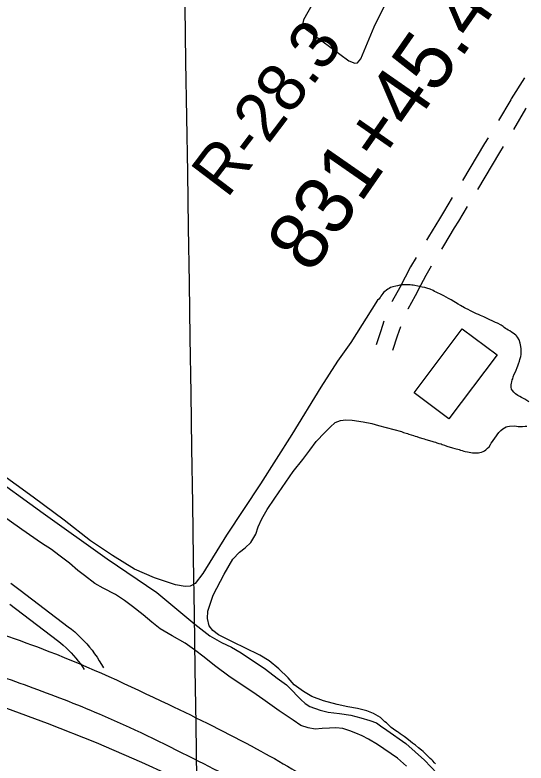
# Model space of a CAD drawing. Extents: x 3823584 to 3861785, y 301729 to 327625.
# Drawn here: x 3837921 to 3838799, y 321169 to 322453 of the extents above; entities that cross this region are included whole.
import ezdxf

# ---------------------------------------------------------------- set-up
doc = ezdxf.new("R2010")
doc.units = 0
for name, color, linetype in [('V-GRID-MAJR', 7, 'Continuous'), ('V-RIVR-EDGE', 7, 'Continuous'), ('V-RIVR-RANG-IDEN', 7, 'Continuous'), ('V-ROAD-CNTR', 7, 'Continuous'), ('V-SITE-OTLN', 7, 'Continuous'), ('V-SITE-VEGE', 7, 'Continuous'), ('V-SURV-IDEN', 7, 'Continuous'), ('V-TOPO-SHOR', 7, 'Continuous'), ('V-WETL-SWMP', 7, 'Continuous')]:
    doc.layers.add(name, color=color, linetype=linetype)

msp = doc.modelspace()

# ---------------------------------------------------------------- linework, layer by layer
at = {"layer": 'V-GRID-MAJR'}
msp.add_spline([(3838444.8910000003, 307319.343), (3838352.38, 313376.366), (3838259.823, 319436.473), (3838167.2660000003, 325496.576), (3838167.219, 325499.664)], degree=3, dxfattribs=at)
at = {"layer": 'V-RIVR-EDGE'}
msp.add_spline([(3836304.3756208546, 325474.18490968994), (3836346.414637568, 325438.3248399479), (3836389.407230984, 325406.0749957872), (3836417.6425015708, 325385.4333151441), (3836442.6682071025, 325366.7281829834), (3836470.247893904, 325340.94515767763), (3836497.8244014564, 325313.8763988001), (3836554.9028376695, 325258.4483785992), (3836598.5128638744, 325215.91107623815), (3836636.356164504, 325181.10248193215), (3836681.25510353, 325139.84773389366), (3836737.070060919, 325093.42302794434), (3836790.9421113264, 325041.2172897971), (3836840.3252216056, 324993.52274652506), (3836889.068644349, 324947.1155264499), (3836934.613629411, 324907.1449223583), (3836980.8110190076, 324871.0299293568), (3837015.471778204, 324849.0866188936), (3837040.494304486, 324829.09575316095), (3837085.3916538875, 324787.1981383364), (3837143.7621821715, 324734.3384060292), (3837181.60866205, 324700.815545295), (3837223.2932671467, 324659.5687453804), (3837272.052586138, 324619.5901931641), (3837314.3832372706, 324579.6275371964), (3837346.4455057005, 324546.7618498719), (3837364.398086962, 324527.4313367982), (3837395.83179523, 324500.35304017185), (3837442.024415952, 324462.30944681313), (3837492.7139249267, 324422.9689925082), (3837554.3051456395, 324372.67277922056), (3837573.562535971, 324361.05348832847), (3837583.2007688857, 324359.1010435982), (3837596.685075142, 324352.6389936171), (3837621.0774516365, 324337.7926517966), (3837648.0333471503, 324319.7256175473), (3837677.5368654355, 324292.00922300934), (3837718.5754244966, 324249.4782791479), (3837753.847257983, 324214.6760433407), (3837781.426944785, 324188.89301803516), (3837800.047826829, 324179.8467839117), (3837819.9544424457, 324170.79737053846), (3837850.7214395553, 324134.0776617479), (3837874.448694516, 324110.2327745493), (3837909.0728923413, 324073.5035280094), (3837941.7780275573, 324040.63625106), (3837989.872225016, 323991.65915346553), (3838022.5821291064, 323960.7204768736), (3838034.1219387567, 323947.83452790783), (3838046.301435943, 323933.66125574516), (3838066.8302532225, 323916.25298453), (3838089.9146413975, 323892.40968695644), (3838140.5946126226, 323849.2120319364), (3838186.144366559, 323811.1700282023), (3838215.652653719, 323785.38223402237), (3838265.675451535, 323736.40036755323), (3838297.1043909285, 323707.3934705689), (3838336.8747022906, 323671.9372406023), (3838359.952731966, 323645.5224758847), (3838385.6228939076, 323627.4586208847), (3838404.2374174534, 323615.8409196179), (3838421.5598489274, 323601.65493045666), (3838441.441030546, 323582.31964850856), (3838460.0476059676, 323567.48761331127), (3838468.395336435, 323563.60974747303), (3838484.446340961, 323555.21273863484), (3838548.5883636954, 323496.55289863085), (3838595.4381578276, 323464.2935167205), (3838649.9785090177, 323422.37205752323), (3838701.302936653, 323379.8156796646), (3838749.433695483, 323345.62451814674), (3838798.2232173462, 323317.86043486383), (3838856.617590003, 323274.6437043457), (3838932.9883882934, 323221.7394625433), (3838989.4684672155, 323184.31330197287), (3839037.599226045, 323150.12214045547), (3839068.4186807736, 323134.6170356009), (3839093.417362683, 323104.98316807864), (3839110.730256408, 323086.93997820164), (3839122.930418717, 323081.1239742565), (3839143.464004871, 323065.6443033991), (3839172.3405526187, 323044.35816634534), (3839190.955076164, 323032.7404650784), (3839215.98555057, 323015.9639332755), (3839242.319244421, 323006.25575686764), (3839316.801182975, 322969.42795358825), (3839341.8396055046, 322955.86575571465), (3839371.3828644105, 322944.2210308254), (3839391.2910696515, 322935.81448423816), (3839417.6104568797, 322920.32050675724), (3839461.26181333, 322894.4977408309), (3839483.709693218, 322873.22750002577), (3839520.2990527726, 322851.27942068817), (3839555.6010891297, 322828.6916538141), (3839599.9048501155, 322806.7244989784), (3839718.698497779, 322751.1438747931), (3839768.138834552, 322726.5925358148), (3839807.9457072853, 322705.9222419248), (3839836.8508682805, 322696.20770701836), (3839865.0988558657, 322680.7089606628), (3839887.567400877, 322667.7959880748), (3839924.172656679, 322652.2765765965), (3839969.7621512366, 322630.306242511), (3840004.4324481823, 322612.2201327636), (3840037.8249596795, 322597.35153619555), (3840085.3541819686, 322579.87650073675), (3840108.4624145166, 322565.6762049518), (3840121.9212867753, 322548.928286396), (3840123.184765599, 322539.92497214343), (3840122.5260025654, 322533.4978939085), (3840117.9957321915, 322521.29455234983), (3840112.8353120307, 322514.2357347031), (3840095.465191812, 322509.1357202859), (3840089.6793907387, 322509.1500269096), (3840085.168195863, 322504.661086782), (3840084.5094328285, 322498.2340085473), (3840085.779270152, 322491.8021614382), (3840130.719539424, 322467.2619498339), (3840169.888314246, 322448.52184592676), (3840197.5093312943, 322439.45335705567), (3840209.076164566, 322437.4961434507), (3840231.586039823, 322441.2977072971), (3840246.3910513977, 322448.9755473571), (3840266.343766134, 322458.5692707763), (3840273.434376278, 322466.26618633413), (3840278.590027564, 322471.3964036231), (3840288.898150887, 322480.37110462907), (3840295.9808129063, 322484.8536862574), (3840301.7666139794, 322484.8393796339), (3840308.195281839, 322484.8234833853), (3840320.395444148, 322479.00747944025), (3840324.873256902, 322469.99621706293), (3840326.781192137, 322461.6341799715), (3840338.324181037, 322450.0339645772), (3840344.7401318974, 322444.87513404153), (3840366.580116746, 322437.7495521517), (3840385.842275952, 322428.05886161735), (3840421.7967168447, 322409.3267058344), (3840466.0957089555, 322385.43095064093), (3840492.411916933, 322368.65123958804), (3840506.526372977, 322357.0446656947), (3840533.4854477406, 322340.2633650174), (3840559.1778644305, 322331.1996450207), (3840587.441748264, 322322.12956652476), (3840611.8452521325, 322311.78329220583), (3840642.0218400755, 322296.27977697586), (3840678.615968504, 322276.2602979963), (3840712.637040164, 322255.60431073), (3840733.1753951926, 322242.05324023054), (3840784.5268464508, 322210.42559773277), (3840835.889425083, 322183.29802273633), (3840892.388579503, 322153.5862635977), (3840923.854080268, 322139.3653026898), (3840950.8242824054, 322127.08406951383), (3840989.3295253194, 322099.98828701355), (3841017.5727440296, 322082.56094030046), (3841061.238407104, 322062.5239754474), (3841092.6943701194, 322044.4458138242), (3841151.0982805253, 322005.0862840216), (3841210.7847452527, 321964.43784139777), (3841240.294622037, 321939.29291400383), (3841299.971549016, 321894.78727066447), (3841335.8926077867, 321862.55491237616), (3841374.3692374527, 321823.88752772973), (3841411.5712609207, 321789.72338983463), (3841444.922442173, 321758.1402568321), (3841469.94019958, 321736.22079074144), (3841482.124465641, 321723.9761189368), (3841496.2198461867, 321704.6551436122), (3841509.051747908, 321694.3374825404), (3841523.1773313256, 321687.23097614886), (3841573.8986327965, 321660.747857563), (3841623.970708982, 321631.69486145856), (3841667.623655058, 321606.5149623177), (3841696.5208679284, 321593.58609348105), (3841738.2626995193, 321575.48249786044), (3841787.074476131, 321556.7185495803), (3841815.992354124, 321552.1469489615), (3841851.3325414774, 321544.9879849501), (3841886.661601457, 321533.32895343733), (3841930.322495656, 321511.36338822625), (3841950.219573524, 321498.4567741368), (3841977.1818275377, 321482.9612070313), (3841998.380535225, 321476.4800815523), (3842052.9924195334, 321463.4876277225), (3842082.546805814, 321456.3429703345), (3842109.5185975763, 321444.7046039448), (3842146.1190845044, 321427.2565921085), (3842196.2006984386, 321402.06079671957), (3842241.1346092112, 321374.94911797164), (3842288.6336286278, 321345.2596135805), (3842321.375325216, 321327.17827270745), (3842366.940975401, 321295.56493683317), (3842395.188962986, 321280.06619047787), (3842429.2227516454, 321264.5531374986), (3842452.3516493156, 321258.7101099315), (3842470.9725313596, 321249.663875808)], degree=3, dxfattribs=at)
at = {"layer": 'V-ROAD-CNTR'}
for points in [[(3838795.988368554, 322344.5592854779), (3838773.2674139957, 322308.30635798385)], [(3838773.268413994, 322308.30835798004), (3838772.3924157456, 322306.91036077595), (3838751.136458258, 322271.31443196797)], [(3838798.6863631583, 322292.37238985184), (3838797.982364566, 322291.2503920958), (3838776.894406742, 322255.9344627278)], [(3838733.589493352, 322241.92849073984), (3838727.524505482, 322231.77351105), (3838689.6965811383, 322168.4816376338)], [(3838759.34544184, 322226.54652150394), (3838753.278453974, 322216.387541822), (3838715.448529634, 322153.0916684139)], [(3838672.081616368, 322139.23669612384), (3838656.9486466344, 322114.2427461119), (3838649.9216606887, 322102.6427693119)], [(3838697.7435650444, 322123.6987271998), (3838682.61059531, 322098.7027771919), (3838675.5816093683, 322087.09880040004)], [(3838649.9216606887, 322102.64176931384), (3838631.1266982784, 322071.61183137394), (3838627.754705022, 322066.03184253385)], [(3838675.5816093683, 322087.0998003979), (3838656.794646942, 322056.08186243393), (3838653.428653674, 322050.51387356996)], [(3838610.081740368, 322036.44790170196), (3838600.6207592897, 322020.22493414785), (3838591.092778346, 322002.34396990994), (3838582.1287962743, 321984.803004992), (3838569.0058225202, 321961.30205199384), (3838568.42582368, 321960.035054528)], [(3838635.99568854, 322021.33393192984), (3838626.8247068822, 322005.60896337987), (3838617.688725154, 321988.4639976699), (3838608.5907433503, 321970.6590332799), (3838595.783768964, 321947.72407914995), (3838595.703769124, 321947.54907949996)], [(3838554.4658516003, 321926.99512060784), (3838549.134862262, 321910.7471531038), (3838541.127878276, 321886.34320191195)], [(3838582.969794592, 321917.6431393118), (3838577.638805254, 321901.395171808), (3838569.6318212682, 321876.99122061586)], [(3837914.3287802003, 321477.55649889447), (3837930.3470027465, 321465.6516226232), (3838012.7239289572, 321402.6811217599), (3838018.2861308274, 321398.3887003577), (3838023.868097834, 321393.76665518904), (3838029.2856966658, 321388.96092887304), (3838034.543354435, 321383.971266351), (3838039.624461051, 321378.80080976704), (3838044.5259682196, 321373.4634935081), (3838049.2432002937, 321367.957365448), (3838053.766521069, 321362.29891065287), (3838058.0949127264, 321356.487913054), (3838062.2228218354, 321350.53386688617), (3838066.1459753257, 321344.43871785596), (3838069.857209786, 321338.2149486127), (3838073.2304969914, 321332.0932107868)], [(3837912.2889972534, 321441.6943773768), (3837994.450071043, 321378.88887824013), (3837999.5498691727, 321374.9532996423), (3838004.3419021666, 321370.985344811), (3838009.000303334, 321366.85307112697), (3838013.512645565, 321362.570733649), (3838017.871538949, 321358.135190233), (3838022.0800317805, 321353.5525064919), (3838026.1287997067, 321348.826634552), (3838030.013478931, 321343.96708934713), (3838033.7310872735, 321338.97608694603), (3838037.2751781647, 321333.8641331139), (3838040.0258204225, 321329.5906387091)]]:
    msp.add_lwpolyline(points, dxfattribs=at)
for points in [[(3837820.0383204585, 321416.434141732), (3837979.6760011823, 321360.54425351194), (3838184.128592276, 321269.847434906), (3838335.998288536, 321193.3505878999), (3838456.602047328, 321122.4437297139), (3838575.2558100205, 321042.7658890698), (3838676.193608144, 320972.2010302)], [(3838708.6275432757, 320880.458213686), (3838559.377841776, 320985.18000424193), (3838364.8532308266, 321104.28076603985), (3838228.3355038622, 321176.0496225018), (3838066.748827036, 321252.678469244), (3837945.153070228, 321300.111374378), (3837826.0583084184, 321341.8592908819), (3837697.7585650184, 321382.57520945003)]]:
    msp.add_spline(points, degree=3, dxfattribs=at)
at = {"layer": 'V-SITE-OTLN'}
msp.add_lwpolyline([(3838689.208, 321914.066), (3838748.946, 321869.065), (3838666.328, 321759.393), (3838606.589, 321804.393)], close=True, dxfattribs=at)
at = {"layer": 'V-SITE-VEGE'}
for points in [[(3838433.576, 322474.482), (3838416.379, 322444.098), (3838414.745, 322435.398), (3838417.096, 322431.03), (3838494.758, 322373.977), (3838505.0270000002, 322369.95900000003), (3838509.3850000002, 322370.329), (3838514.964, 322377.026), (3838538.244, 322432.316), (3838577.094, 322511.271)], [(3838604.998, 321989.051), (3838602.594, 321989.031), (3838599.886, 321989.305), (3838597.484, 321989.28500000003), (3838593.875, 321989.553), (3838587.867, 321989.5), (3838584.563, 321989.17), (3838577.969, 321987.609), (3838574.966, 321987.282), (3838569.873, 321985.731), (3838566.275, 321984.797), (3838563.5840000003, 321983.272), (3838561.191, 321982.049), (3838559.105, 321980.226), (3838556.119, 321978.096), (3838554.032, 321976.278), (3838552.846, 321974.461), (3838549.2800000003, 321969.923), (3838548.097, 321967.809), (3838546.018, 321965.085), (3838543.935, 321962.964), (3838497.867, 321890.739), (3838474.9050000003, 321858.487), (3838446.329, 321813.988), (3838396.844, 321732.375), (3838342.981, 321647.914), (3838284.347, 321559.717), (3838243.864, 321494.09500000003), (3838230.6950000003, 321476.939), (3838221.856, 321472.433), (3838213.433, 321471.589), (3838197.211, 321474.755), (3838160.934, 321486.646), (3838126.4560000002, 321501.699), (3838088.9620000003, 321524.987), (3838051.1780000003, 321550.355), (3838005.827, 321585.771), (3837952.776, 321625.191), (3837893.6010000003, 321667.618)], [(3838803.605, 321788.607), (3838796.654, 321793.053), (3838794.541, 321794.235), (3838790.619, 321796.005), (3838787.895, 321798.083), (3838784.876, 321799.558), (3838780.344, 321802.523), (3838777.616, 321805.202), (3838775.185, 321808.184), (3838773.964, 321810.277), (3838773.3310000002, 321813.878), (3838773.295, 321817.783), (3838773.87, 321820.794), (3838774.153, 321822.89900000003), (3838775.023, 321826.213), (3838775.906, 321828.324), (3838776.7800000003, 321831.337), (3838778.241, 321836.158), (3838780.307, 321840.082), (3838784.423, 321850.33400000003), (3838785.593, 321853.951), (3838787.3540000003, 321858.47500000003), (3838787.932, 321861.18200000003), (3838788.8140000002, 321863.29600000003), (3838789.687, 321866.607), (3838790.256, 321869.919), (3838790.514, 321874.728), (3838790.488, 321877.732), (3838790.164, 321880.431), (3838789.208, 321886.434), (3838788.5810000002, 321889.434), (3838786.725, 321895.128), (3838783.9790000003, 321899.91000000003), (3838782.4590000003, 321901.7), (3838780.946, 321903.189), (3838779.129, 321904.674), (3838776.7090000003, 321906.455), (3838773.688, 321908.231), (3838770.964, 321910.31), (3838767.947, 321911.784), (3838765.832, 321913.26900000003), (3838763.413, 321914.75), (3838761.2970000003, 321916.232), (3838759.4790000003, 321918.018), (3838755.85, 321920.39400000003), (3838749.812, 321923.64400000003), (3838746.497, 321924.814), (3838740.7600000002, 321927.76900000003), (3838736.541, 321929.231), (3838725.98, 321934.24700000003), (3838720.5500000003, 321936.602), (3838716.93, 321938.371), (3838713.913, 321939.547), (3838708.174, 321942.799), (3838703.349, 321944.859), (3838699.423, 321946.928), (3838695.202, 321948.693), (3838692.786, 321950.174), (3838686.443, 321953.723), (3838681.913, 321956.38800000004), (3838670.131, 321963.492), (3838665.2970000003, 321966.155), (3838657.45, 321970.289), (3838654.126, 321972.364), (3838644.166, 321977.083), (3838641.756, 321977.961), (3838639.036, 321979.741), (3838633.91, 321981.797), (3838628.184, 321983.55), (3838625.169, 321984.726), (3838620.653, 321985.586), (3838615.836, 321986.745), (3838604.998, 321989.051)], [(3838578.014, 321222.579), (3838574.9930000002, 321224.355), (3838567.434, 321229.696), (3838563.188, 321233.86100000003), (3838561.3740000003, 321235.348), (3838558.949, 321237.73), (3838556.528, 321239.514), (3838551.0700000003, 321244.871), (3838548.65, 321246.956), (3838536.806, 321253.854), (3838525.245, 321258.577), (3838509.522, 321262.429), (3838492.8030000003, 321265.397), (3838474.305, 321269.167), (3838451.169, 321275.538), (3838430.912, 321283.28), (3838416.502, 321291.58), (3838400.725, 321303.356), (3838390.198, 321315.3), (3838374.34, 321330.642), (3838357.682, 321344.007), (3838341.791, 321353.903), (3838316.12, 321366.623), (3838296.961, 321375.84500000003), (3838270.595, 321388.87200000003), (3838260.736, 321396.452), (3838254.938, 321404.409), (3838251.937, 321416.707), (3838252.509, 321429.773), (3838261.774, 321456.954), (3838280.597, 321492.696), (3838295.502, 321518.853), (3838306.7600000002, 321530.77), (3838316.4080000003, 321538.243), (3838326.4620000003, 321547.195), (3838334.961, 321561.507), (3838338.895, 321574.159), (3838344.919, 321588.188), (3838354.022, 321604.179), (3838367.3030000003, 321623.61), (3838398.955, 321668.984), (3838415.3140000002, 321689.488), (3838427.291, 321705.956), (3838438.465, 321720.352), (3838453.311, 321736.11100000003), (3838462.275, 321745.27), (3838471.233, 321753.042), (3838479.968, 321756.458), (3838489.186, 321757.988), (3838500.47, 321757.232), (3838519.367, 321754.25), (3838533.812, 321751.495), (3838545.477, 321748.26), (3838585.014, 321737.674), (3838588.332, 321736.201), (3838590.74, 321735.621), (3838592.8540000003, 321734.739), (3838595.262, 321734.159), (3838597.3710000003, 321733.276), (3838605.205, 321730.944), (3838608.521, 321729.77), (3838610.929, 321729.193), (3838615.449, 321727.73), (3838621.4760000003, 321725.981), (3838623.588, 321725.099), (3838626.899, 321724.226), (3838632.929, 321722.176), (3838638.651, 321720.726), (3838640.461, 321719.842), (3838643.47, 321719.266), (3838645.5810000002, 321718.38300000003), (3838649.198, 321717.214), (3838652.811, 321716.346), (3838654.9220000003, 321715.463), (3838658.838, 321714.29600000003), (3838662.7600000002, 321712.829), (3838672.701, 321709.913), (3838676.318, 321708.743), (3838683.846, 321706.708), (3838686.259, 321705.827), (3838688.968, 321705.252), (3838691.987, 321703.777), (3838694.094, 321703.494), (3838698.006, 321702.628), (3838701.316, 321702.05700000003), (3838703.722, 321701.776), (3838706.733, 321701.205), (3838708.838, 321700.922), (3838716.95, 321700.996), (3838719.645, 321701.92), (3838722.045, 321702.542), (3838725.042, 321703.472), (3838727.434, 321704.695), (3838729.525, 321706.214), (3838732.505, 321708.946), (3838735.183, 321711.674), (3838737.8540000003, 321715.604), (3838739.036, 321717.72000000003), (3838741.112, 321720.745), (3838741.997, 321722.553), (3838744.971, 321726.184)], [(3838744.971, 321726.184), (3838752.092, 321736.164), (3838755.366, 321739.498), (3838758.645, 321742.533), (3838764.627, 321745.591), (3838766.723, 321746.51300000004), (3838770.323, 321747.146), (3838779.336, 321747.22500000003), (3838785.056, 321746.074), (3838790.463, 321746.124), (3838792.5640000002, 321746.443), (3838797.068, 321746.783), (3838799.769, 321747.109)], [(3838643.109, 321167.574), (3838641.594, 321169.061), (3838638.557, 321172.641), (3838636.736, 321174.426), (3838634.315, 321176.507), (3838632.194, 321178.592), (3838628.8570000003, 321181.869), (3838626.127, 321184.849), (3838624.61, 321186.338), (3838621.8880000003, 321188.418), (3838619.463, 321190.798), (3838614.0160000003, 321195.257), (3838609.17, 321199.422), (3838607.3570000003, 321200.606), (3838603.7260000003, 321203.277), (3838596.765, 321208.925), (3838591.625, 321212.48), (3838589.204, 321214.565), (3838582.853, 321219.015), (3838579.826, 321221.391), (3838578.014, 321222.579)]]:
    msp.add_lwpolyline(points, dxfattribs=at)
at = {"layer": 'V-TOPO-SHOR'}
for points in [[(3837871.075, 321668.404), (3837969.75, 321597.918), (3838079.5840000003, 321519.037), (3838164.846, 321461.62200000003), (3838230.1920000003, 321407.395), (3838255.96, 321387.015), (3838275.93, 321375.593), (3838292.9420000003, 321367.86), (3838309.7460000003, 321357.84500000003), (3838351.636, 321329.837), (3838371.682, 321314.54600000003), (3838387.3880000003, 321303.151), (3838398.04, 321292.875), (3838405.529, 321284.5), (3838411.839, 321278.117), (3838419.3370000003, 321271.13300000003), (3838427.637, 321265.829), (3838445.551, 321259.377), (3838459.1210000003, 321256.424), (3838478.647, 321254.13), (3838497.769, 321250.848), (3838515.298, 321246.184), (3838530.5470000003, 321242.131), (3838541.83, 321238), (3838548.842, 321232.903)], [(3838543.8000000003, 321200.79600000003), (3838528.2800000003, 321210.01), (3838517.6040000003, 321215.724), (3838506.4220000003, 321220.351), (3838496.131, 321224.375), (3838484.051, 321228.016), (3838472.157, 321229.27400000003), (3838461.544, 321228.938), (3838448.646, 321227.92), (3838436.64, 321227.195), (3838424.848, 321229.049), (3838412.0810000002, 321233.487), (3838398.74, 321242.291), (3838374.93, 321258.196), (3838347.079, 321278.686), (3838329.6920000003, 321290.489), (3838290.663, 321316.103), (3838264, 321336.38800000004), (3838246.129, 321350.374), (3838229.639, 321362.867), (3838213.541, 321374.86), (3838191.296, 321386.988), (3838170.8370000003, 321399.305), (3838156.122, 321410.397), (3838141.22, 321423.176), (3838122.856, 321437.662), (3838109.6240000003, 321447.656), (3838094.211, 321458.158), (3838072.95, 321468.99), (3838058.416, 321476.81), (3838040.643, 321490.599), (3838029.289, 321499.489), (3838015.076, 321511.572), (3837996.9080000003, 321525.859), (3837984.0670000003, 321535.05700000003), (3837967.075, 321546.261), (3837932.99, 321569.465), (3837875.304, 321610.46)], [(3838548.842, 321232.903), (3838559.938, 321225.42), (3838592.544, 321202.273), (3838624.512, 321173.607), (3838646.0810000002, 321151.053)], [(3838593.5810000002, 321163.681), (3838578.292, 321177.33), (3838543.8000000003, 321200.79600000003)]]:
    msp.add_lwpolyline(points, dxfattribs=at)
at = {"layer": 'V-WETL-SWMP'}
msp.add_lwpolyline([(3837906.954, 321263.14), (3837976.779, 321237.044), (3838060.7970000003, 321204.145), (3838138.486, 321170.492), (3838228.782, 321129.256)], dxfattribs=at)

# ---------------------------------------------------------------- texts
at = {"layer": 'V-RIVR-RANG-IDEN'}
msp.add_text('R-28.3', height=82.99999799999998, rotation=52.84381706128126, dxfattribs=at).set_placement((3838285.185340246, 322136.0981976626))
at = {"layer": 'V-SURV-IDEN'}
msp.add_text('831+45.4', height=100.00000000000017, rotation=55.19805555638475, dxfattribs=at).set_placement((3838429.525926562, 322006.03568655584))

doc.saveas('drawing.dxf')
